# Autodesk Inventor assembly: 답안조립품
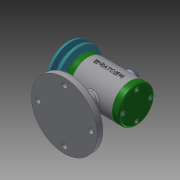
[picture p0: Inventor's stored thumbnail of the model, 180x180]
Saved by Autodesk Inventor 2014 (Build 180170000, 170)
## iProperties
Created: 2018-12
Part Number: 답안조립품
Document SubType Name: Assembly
Designer: 601-23
Author: 601-23
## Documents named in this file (15)
- C:\Users\601-23\Desktop\481208V1009\답안조립품.iam
- C:\Users\601-23\Desktop\481208V1009\본체.ipt
- C:\Users\601-23\Desktop\481208V1009\V벨트풀리.ipt
- C:\Users\601-23\Desktop\481208V1009\고무캡.ipt
- C:\Users\601-23\Desktop\481208V1009\너트 M8.ipt
- 너트 M8.ipt
- C:\Users\601-23\Desktop\481208V1009\뒤커버.ipt
- C:\Users\601-23\Desktop\481208V1009\베어링 15 x 32 x 9.ipt
- C:\Users\601-23\Desktop\481208V1009\볼트 M4 x 12.ipt
- C:\Users\601-23\Desktop\481208V1009\스프링와셔 8.ipt
- C:\Users\601-23\Desktop\481208V1009\앞커버.ipt
- C:\Users\601-23\Desktop\481208V1009\오일 실 15 25 7.ipt
- C:\Users\601-23\Desktop\481208V1009\와셔 8x17.ipt
- C:\Users\601-23\Desktop\481208V1009\축.ipt
- C:\Users\601-23\Desktop\481208V1009\키 3 x 3 x 12.ipt
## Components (2 placed, 2 different names)
1. V벨트풀리:1 — 각도:1
2. 고무캡:1 — 각도:5
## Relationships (2: Angle 2)
- 각도:1 [Angle]: V벨트풀리:1
- 각도:5 [Angle]: 고무캡:1
